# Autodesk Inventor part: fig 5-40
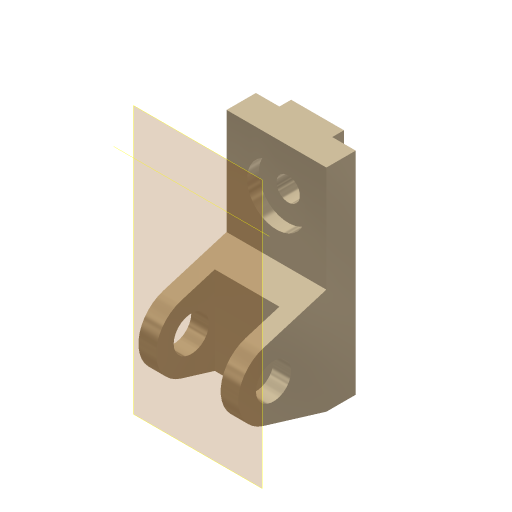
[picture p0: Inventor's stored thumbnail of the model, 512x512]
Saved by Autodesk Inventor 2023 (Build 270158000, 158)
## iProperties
Created: 2001-11
Part Number: fig 5-40
Document SubType Name: Modeling
Designer: Renu Muthoo
Density: 1 g/cm^3
Material: Generic
Appearance: Metal-Titanium (Polished)
Control State: 0
Master: False
Checked Out: False
Shininess: 65.0
Angle Display Precision: 2
Document Length Units: 11269
Document Angle Units: 11279
Document Time Units: 11290
Document Mass Units: 11283
Document Length Units Precision: 3
Document Angle Units Precision: 2
Density: 0.0
Volumn: 0.0
Area: 0.0
PropertySet Name: Model Information
Author: Renu Muthoo
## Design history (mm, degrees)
node "Sketch1"
sketch "Sketch2"
  geometry: L1 (33.257, 104.664)-(33.257, -75.336); L2 (33.257, -75.336)-(8.257, -75.336); L3 (8.257, -75.336)-(-45.451, -59.045); L4 (-45.451, -1.628)-(8.257, 14.664); L5 (8.257, 14.664)-(8.257, 104.664); L6 (8.257, 104.664)-(33.257, 104.664); C1 r 15 at (-36.743, -30.336); A1 r 30 centre (-36.743, -30.336) between (-45.451, -1.628) and (-45.451, -59.045)
  constraints: 12 end point, 2 centre point, 2 equal length, 2 parallel, 2 point on circle, 2 tangent, 1 coincident, 1 perpendicular, 1 vertical
  dimensions: "d0" = 180 distance of L1.start L1.end; "d1" = 30 radius of A1; "d2" = 25 distance of L5.end L1.start; "d3" = 45 distance from line of L2 A1.centre; "d4" = 70 distance from line of L1 A1.centre; "d5" = 30 diameter of C1
extrude "Extrusion1" new body sketch "Sketch2" distance "d6" = 85; taper "d7" = 0 deg
workplane "Work Plane1"
sketch "Sketch3"
  geometry: L1 (15, 62.364)-(70, 62.364); L2 (70, 62.364)-(70, -52.386); L3 (70, -52.386)-(15, -52.386); L4 (15, -52.386)-(15, 62.364); L5 (0, -45)-(0, -28.708) reference
  constraints: 8 end point, 2 parallel, 1 horizontal, 1 perpendicular
  dimensions: "d8" = 55 distance of L1.start L1.end; "d9" = 15 distance between parallel lines of L5 L4
extrude "Extrusion2" cut sketch "Sketch3" distance "d10" = 50; taper "d11" = 0 deg
sketch "Sketch4"
  geometry: L1 (0, 25)-(85, 25) reference; L2 (0, 0)-(0, 25) reference; L3 (20, 25)-(65, 25); L4 (65, 25)-(65, 35); L5 (65, 35)-(20, 35); L6 (20, 35)-(20, 25)
  constraints: 8 end point, 2 parallel, 1 horizontal, 1 perpendicular, 1 point on line
  dimensions: "d12" = 45 distance of L4.end L5.end; "d13" = 10 distance of L3.end L4.end; "d14" = 20 distance between parallel lines of L2 L6
extrude "Extrusion3" join sketch "Sketch4" stored distance "d15" = 50; taper "d16" = 0 deg
sketch "Sketch5"
  geometry: L1 (85, 0)-(85, 90) reference; L2 (0, 90)-(85, 90) reference; 1 further point
  dimensions: "d17" = 42 distance from line of L2 point (42.5, 48); "d18" = 42.5 distance from line of L1 point (42.5, 48)
hole "Hole1" sketch "Sketch5" at (42.5, 48) diameter "d19" = 20; stored, may be unused: countersink angle "d23" = 82 deg, drill point angle "d25" = 118 deg; dims "d20" = 6, "d21" = 50, "d22" = 10, "d24" = 8
workaxis "Work Axis1"
  workplane "Work Plane3"
body "Solid1"
